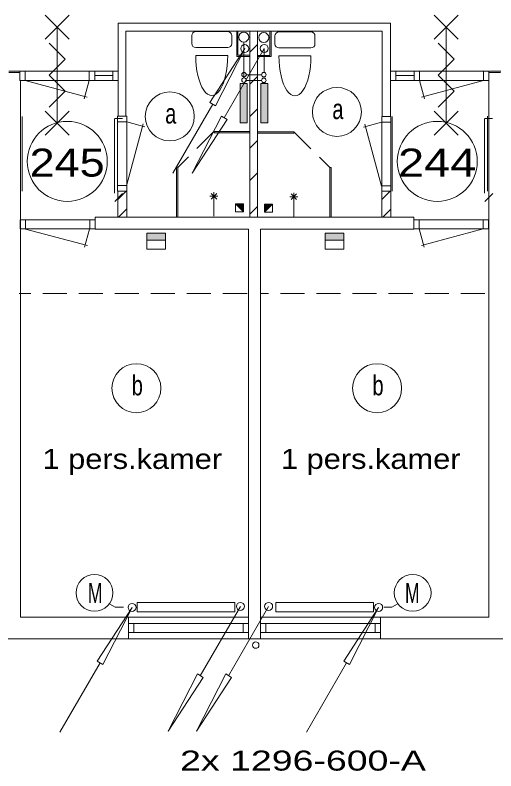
# Model space of a CAD drawing. Extents: x 295824 to 414724, y 24924 to 109024.
# Drawn here: x 314024 to 320029, y 85900 to 95351 of the extents above; entities that cross this region are included whole.
import ezdxf
from ezdxf.enums import TextEntityAlignment as Align

# ---------------------------------------------------------------- set-up
doc = ezdxf.new("R2010")
doc.units = 0
doc.header["$LTSCALE"] = 100
doc.linetypes.add('LONG_DASHED', pattern=[7.5, 6, -1.5])
doc.linetypes.add('MEDIUM_DASHED', pattern=[4.5, 3, -1.5])
doc.layers.add('16', color=7, linetype='Continuous', lineweight=13)
doc.layers.add('61', color=7, linetype='Continuous', lineweight=13)

msp = doc.modelspace()

# ---------------------------------------------------------------- hatches: boundary and pattern name
at = {"layer": '16'}
for points in [[(316835.4, 94004.5), (316920.8, 94004.5), (316920.8, 94496.7), (316835.4, 94496.7)], [(317094.6, 94004.5), (317180, 94004.5), (317180, 94496.7), (317094.6, 94496.7)], [(315902.2, 92624.5), (315670.7, 92624.5), (315670.7, 92538), (315902.2, 92538)], [(318129.9, 92624.5), (317898.4, 92624.5), (317898.4, 92538), (318129.9, 92538)]]:
    msp.add_hatch(color=256, dxfattribs=at).paths.add_polyline_path(points)
at = {"layer": '61'}
for points in [[(316775.3, 92991.3), (316875.3, 92891.3), (316875.3, 92991.3)], [(317237.7, 92985.9), (317137.7, 92885.9), (317137.7, 92985.9)]]:
    msp.add_hatch(color=256, dxfattribs=at).paths.add_polyline_path(points)

# ---------------------------------------------------------------- linework, layer by layer
at = {"layer": '16'}
for p, q in [((316882.7, 95010.5), (316882.7, 94570.9)), ((317136.2, 94934), (316636.2, 94068)), ((317103, 94535.5), (316911.2, 94535.5)), ((315992.3, 93373.3), (316492.3, 94239.3)), ((315670.7, 92538), (315670.7, 92424.1)), ((317898.4, 92538), (317898.4, 92424.1)), ((316837.4, 87956.8), (316337.4, 87090.8)), ((317190.8, 87956.8), (316690.8, 87090.8)), ((314584.5, 86385.7), (315084.5, 87251.7)), ((317664.9, 86385.7), (318164.9, 87251.7))]:
    msp.add_line(p, q, dxfattribs=at)
at = {"layer": '16', "linetype": 'LONG_DASHED'}
for p, q in [((317133.8, 94929.7), (317133.8, 94632)), ((316911.4, 94606.2), (317102.9, 94606.2))]:
    msp.add_line(p, q, dxfattribs=at)
at = {"layer": '16'}
for points in [[(316892.3, 94932.3), (316528.3, 94218.3), (316456.3, 94260.3)], [(316835.4, 94004.5), (316920.8, 94004.5), (316920.8, 94496.7), (316835.4, 94496.7)], [(317094.6, 94004.5), (317180, 94004.5), (317180, 94496.7), (317094.6, 94496.7)], [(316236.2, 93375), (316600.2, 94089), (316672.2, 94047)], [(315902.2, 92624.5), (315670.7, 92624.5), (315670.7, 92538), (315902.2, 92538)], [(318129.9, 92624.5), (317898.4, 92624.5), (317898.4, 92538), (318129.9, 92538)], [(315547.4, 88006.2), (316766.8, 88006.2), (316766.8, 87888.3), (315547.4, 87888.3)], [(317279.7, 88006.2), (318499, 88006.2), (318499, 87888.3), (317279.7, 87888.3)], [(315484.5, 87944.7), (315120.5, 87230.7), (315048.5, 87272.7)], [(318564.9, 87944.7), (318200.9, 87230.7), (318128.9, 87272.7)], [(315937.4, 86397.8), (316301.4, 87111.8), (316373.4, 87069.8)], [(316290.8, 86397.8), (316654.8, 87111.8), (316726.8, 87069.8)]]:
    msp.add_lwpolyline(points, close=True, dxfattribs=at)
for points in [[(315902.2, 92538), (315902.2, 92424.1), (315670.7, 92424.1)], [(318129.9, 92538), (318129.9, 92424.1), (317898.4, 92424.1)], [(315376.1, 87947.9), (315273.6, 87947.9), (315207.1, 87986.3)], [(318628.8, 87947.9), (318731.4, 87947.9), (318797.8, 87986.3)]]:
    msp.add_lwpolyline(points, dxfattribs=at)
for centre, radius in [((316892.3, 94932), 50), ((317136.2, 94934.3), 50), ((316883.5, 94606.2), 27.9), ((317130.9, 94606.2), 27.9), ((316883.5, 94538.4), 27.9), ((317130.9, 94535.5), 27.9), ((315015.6, 88125.9), 229.9), ((318989.4, 88125.9), 229.9), ((315484.5, 87944.4), 50), ((316837.4, 87957.1), 50), ((317190.8, 87957.1), 50), ((318564.9, 87944.4), 50)]:
    msp.add_circle(centre, radius, dxfattribs=at)
at = {"layer": '61'}
for p, q in [((314400.4, 95051.1), (314700.4, 95351.1)), ((314700.4, 95051.1), (314400.4, 95351.1)), ((319256.2, 95051.1), (319556.2, 95351.1)), ((319556.2, 95051.1), (319256.2, 95351.1)), ((314550.4, 95201.1), (314550.4, 94001.1)), ((319406.2, 95201.1), (319406.2, 94001.1)), ((315407, 94086.3), (315407, 95148.4)), ((316230.2, 94995.4), (316230.2, 95095.4)), ((316280.2, 95145.4), (316680.2, 95145.4)), ((316730.2, 95095.4), (316730.2, 94995.4)), ((316807, 94848.4), (316807, 95148.4)), ((316957, 92823.4), (316957, 95148.4)), ((317053.3, 92823.4), (317053.3, 95148.4)), ((317207.1, 95147.9), (317207.1, 94847.9)), ((317269.6, 94990.5), (317269.6, 95090.5)), ((317319.6, 95140.5), (317719.6, 95140.5)), ((317769.6, 95090.5), (317769.6, 94990.5)), ((317052.8, 94982.4), (316957, 94886.7)), ((316680.2, 94945.4), (316280.2, 94945.4)), ((317719.6, 94940.5), (317319.6, 94940.5)), ((316280.2, 94845.4), (316680.2, 94845.4)), ((316957, 94848.4), (316807, 94848.4)), ((317207.1, 94847.9), (317057.1, 94847.9)), ((317319.6, 94840.5), (317719.6, 94840.5)), ((313944.8, 94648.3), (314086, 94648.3)), ((313944.8, 94633.3), (314086, 94633.3)), ((314150.8, 94648.3), (314150.8, 94534.3)), ((314950.8, 94648.3), (314950.8, 94534.3)), ((315017.8, 94648.3), (315017.8, 94534.3)), ((315243.8, 94648.3), (315243.8, 94534.3)), ((318712.3, 94084.9), (318712.3, 94650.7)), ((318780.5, 94648.3), (318780.5, 94534.3)), ((319006.5, 94648.3), (319006.5, 94534.3)), ((319073.5, 94648.3), (319073.5, 94534.3)), ((319873.5, 94648.3), (319873.5, 94534.3)), ((319944.4, 94633.3), (320085.5, 94633.3)), ((319949.3, 94648.3), (320090.5, 94648.3)), ((314090.1, 94533.5), (314090.1, 87823.4)), ((314150.1, 94533.7), (314922.8, 94326.6)), ((314948.5, 94533.1), (314887.7, 94306.2)), ((315243.8, 94594.2), (315017.8, 94594.2)), ((315312.3, 94086.3), (315312.3, 94548.4)), ((317052.8, 94581.5), (316957, 94485.8)), ((318780.5, 94594.2), (319006.5, 94594.2)), ((319075.8, 94533.1), (319136.6, 94306.2)), ((319874.2, 94533.7), (319101.5, 94326.6)), ((319940.1, 94548.4), (319940.1, 87823.4)), ((314400.4, 93851.1), (314700.4, 94151.1)), ((314700.4, 93851.1), (314400.4, 94151.1)), ((317052.8, 94178.2), (316957, 94082.4)), ((319256.2, 93851.1), (319556.2, 94151.1)), ((319556.2, 93851.1), (319256.2, 94151.1)), ((314112.5, 93148.9), (314112.5, 94081.3)), ((315264.9, 93123.7), (315264.9, 94057.7)), ((315367.2, 94058.5), (315272.4, 94058.5)), ((315304.8, 93151.5), (315304.8, 94085.5)), ((315407, 94086.3), (315312.3, 94086.3)), ((318712.3, 94084.9), (318607, 94084.9)), ((318718.2, 93148.9), (318718.2, 94081.3)), ((318734.1, 93148.9), (318734.1, 94081.3)), ((319886.5, 93123.7), (319886.5, 94057.7)), ((319988.8, 94058.5), (319894, 94058.5)), ((319926.4, 93151.5), (319926.4, 94085.5)), ((315304.8, 94018.5), (315418.8, 94018.5)), ((315416.8, 93217.8), (315623.9, 93990.5)), ((315417.5, 94016.2), (315644.3, 93955.4)), ((318600.4, 94011.9), (318373.6, 93951.2)), ((318601.1, 93213.5), (318394, 93986.3)), ((318718.2, 94014.3), (318604.2, 94014.3)), ((316958.2, 93897), (316508.7, 93897)), ((316508.7, 93897), (316508.7, 93879)), ((316957.8, 93879), (316508.7, 93879)), ((317054.8, 93891.6), (317504.3, 93891.6)), ((317055.2, 93873.6), (317504.3, 93873.6)), ((317504.3, 93891.6), (317504.3, 93873.6)), ((317052.8, 93782.2), (316957, 93686.4)), ((316057.8, 92829), (316057.8, 93449.5)), ((317052.8, 93377.6), (316957, 93281.8)), ((317955.2, 92823.6), (317955.2, 93444.1)), ((315304.8, 93218.5), (315418.8, 93218.5)), ((318718.2, 93214.3), (318604.2, 93214.3)), ((315367.3, 93118.9), (315267.6, 93019.2)), ((315418.2, 93151.5), (315304.2, 93151.5)), ((315417.5, 93148), (315307.5, 93148)), ((315307.5, 93148), (315307.5, 92823.9)), ((315407.2, 93146.8), (315307.5, 93047.1)), ((315417.5, 93148), (315417.5, 92823.9)), ((316543, 93050.1), (316472.3, 93120.8)), ((316543, 93120.8), (316472.3, 93050.1)), ((316507.6, 93035.5), (316507.6, 93135.5)), ((317470, 93044.8), (317540.7, 93115.5)), ((317470, 93115.5), (317540.7, 93044.8)), ((317505.4, 93030.1), (317505.4, 93130.1)), ((318705.6, 93146.8), (318605.9, 93047.1)), ((318716.4, 93148), (318606.5, 93148)), ((318606.5, 93148), (318606.5, 92823.9)), ((318716.4, 93148), (318716.4, 92823.9)), ((319988.9, 93118.9), (319889.2, 93019.2)), ((316557.6, 93085.5), (316457.6, 93085.5)), ((316507.6, 93035.5), (316507.6, 92835.5)), ((317455.4, 93080.1), (317555.4, 93080.1)), ((317505.4, 93030.1), (317505.4, 92830.1)), ((315415.8, 92924.2), (315316.1, 92824.5)), ((317052.8, 92959.5), (316957, 92863.7)), ((318717.9, 92924.2), (318618.2, 92824.5)), ((315417.5, 92823.9), (315307.5, 92823.9)), ((318716.4, 92823.9), (318606.5, 92823.9)), ((314155.4, 92790.9), (314155.4, 92676.9)), ((314955.4, 92790.9), (314955.4, 92676.9)), ((315022.4, 92790.9), (315022.4, 92676.9)), ((319003.1, 92791.9), (319003.1, 92677.9)), ((319070.1, 92791.9), (319070.1, 92677.9)), ((319870.1, 92791.9), (319870.1, 92677.9)), ((314154.7, 92676.2), (314927.4, 92469.2)), ((314953.1, 92675.6), (314892.3, 92448.8)), ((316940.1, 87553.4), (316940.1, 92673.4)), ((317090.1, 87553.4), (317090.1, 92673.4)), ((319072.4, 92676.7), (319133.2, 92449.8)), ((319870.9, 92677.3), (319098.1, 92470.3)), ((314090.1, 87823.4), (316940.1, 87823.4)), ((315441, 87552.1), (315441, 87822.1)), ((319940.1, 87823.4), (317090.1, 87823.4)), ((318589.5, 87552.2), (318589.5, 87822.2)), ((315508.1, 87630.5), (315508.1, 87744.3)), ((316873.1, 87629.9), (316873.1, 87743.9)), ((317156.6, 87630.8), (317156.6, 87744.8)), ((318520.9, 87630.5), (318520.9, 87744.2)), ((326233, 87553.4), (307806, 87553.4))]:
    msp.add_line(p, q, dxfattribs=at)
at = {"layer": '61', "linetype": 'MEDIUM_DASHED'}
for p, q in [((316506.6, 93896.5), (316059.7, 93449.6)), ((317506.4, 93891.2), (317953.3, 93444.3)), ((316920.4, 91870), (314073.3, 91870)), ((319889.8, 91870), (317090.1, 91870))]:
    msp.add_line(p, q, dxfattribs=at)
at = {"layer": '61'}
for points in [[(318712.3, 94648.4), (318712.3, 95248.4), (315312.3, 95248.4), (315312.3, 94648.4)], [(318607, 94084.9), (318607, 95148.4), (315407, 95148.4)], [(316957, 94833.4), (316792, 94833.4), (316792, 95148.4)], [(317222.1, 95147.9), (317222.1, 94832.9), (317057.1, 94832.9)], [(314450.4, 95001.1), (314650.4, 94801.1), (314450.4, 94601.1), (314650.4, 94401.1), (314450.4, 94201.1)], [(319306.2, 95001.1), (319506.2, 94801.1), (319306.2, 94601.1), (319506.2, 94401.1), (319306.2, 94201.1)], [(316039.8, 92829), (316039.8, 93449.5), (316057.8, 93449.5)], [(317973.2, 92823.6), (317973.2, 93444.1), (317955.2, 93444.1)], [(316875.3, 92891.3), (316875.3, 92991.3), (316775.3, 92991.3)], [(317137.7, 92885.9), (317137.7, 92985.9), (317237.7, 92985.9)], [(317087.3, 92673.4), (319002.3, 92673.4), (319002.3, 92823.4), (315022.9, 92823.4)], [(316937.3, 92673.4), (315022.9, 92673.4), (315022.9, 92823.4)], [(314088.4, 92790.9), (314088.4, 92676.9), (315022.4, 92676.9)], [(315022.4, 92790.9), (314088.4, 92790.9), (314088.4, 92676.9)], [(319937.1, 92791.9), (319937.1, 92677.9), (319003.1, 92677.9)], [(319003.1, 92791.9), (319937.1, 92791.9), (319937.1, 92677.9)]]:
    msp.add_lwpolyline(points, dxfattribs=at)
for points in [[(315310.8, 94648.3), (315310.8, 94534.3), (314083.8, 94534.3), (314083.8, 94648.3)], [(315310.9, 94648.3), (315310.9, 94534.3), (314083.9, 94534.3), (314083.9, 94648.3)], [(319940.5, 94648.3), (319940.5, 94534.3), (318714.1, 94534.3), (318714.1, 94648.3)], [(319940.5, 94648.3), (319940.5, 94534.3), (318714.1, 94534.3), (318714.1, 94648.3)], [(315304.8, 93151.5), (315304.8, 94085.5), (315418.8, 94085.5), (315418.8, 93151.5)], [(318718.2, 94082.2), (318604.2, 94082.2), (318604.2, 93148.2), (318718.2, 93148.2)], [(316875.3, 92891.3), (316775.3, 92891.3), (316775.3, 92991.3)], [(316775.3, 92991.3), (316875.3, 92891.3), (316875.3, 92991.3)], [(317137.7, 92885.9), (317237.7, 92885.9), (317237.7, 92985.9)], [(317237.7, 92985.9), (317137.7, 92885.9), (317137.7, 92985.9)], [(315441.2, 87630.3), (315441.2, 87744.3), (316939.9, 87744.3), (316939.9, 87630.3)], [(317090.2, 87630.5), (317090.2, 87744.5), (318589.6, 87744.5), (318589.6, 87630.5)]]:
    msp.add_lwpolyline(points, close=True, dxfattribs=at)
for centre, radius in [((316879.5, 95075.9), 62.5), ((317129.5, 95070.4), 62.5), ((318044.2, 94140.2), 306.3), ((315956.1, 94084.5), 306.3), ((314675.2, 93521.8), 500), ((319296.8, 93521.8), 500), ((315538.5, 90685.4), 306.3), ((318545.3, 90685.4), 306.3), ((317029.6, 87473.2), 40)]:
    msp.add_circle(centre, radius, dxfattribs=at)
for centre, start, end in [((316280.2, 95095.4), 90, 180), ((316680.2, 95095.4), 0, 90), ((317319.6, 95090.5), 90, 180), ((317719.6, 95090.5), 0, 90), ((316280.2, 94995.4), 180, 270), ((316680.2, 94995.4), 270, 0), ((317319.6, 94990.5), 180, 270), ((317719.6, 94990.5), 270, 0)]:
    msp.add_arc(centre, 50, start, end, dxfattribs=at)
for centre in [(316480.2, 94845.4), (317519.6, 94840.5)]:
    msp.add_ellipse(centre, major_axis=(0, -500), ratio=0.4, start_param=4.712389, end_param=7.853982, dxfattribs=at)

# ---------------------------------------------------------------- texts
at = {"layer": '16'}
for s, width, p in [('M', 0.65, (314933.3, 87999.3)), ('M', 0.65, (318894.5, 87999.3)), ('2x 1296-600-A', 1.4, (316084.4, 85903.8))]:
    msp.add_text(s, height=250, dxfattribs=dict(at, width=width)).set_placement(p)
at = {"layer": '61'}
for s, width, p in [('a', 0.75, (317986.2, 94051)), ('a', 0.75, (315898.1, 93995.3)), ('b', 0.75, (315480.5, 90596.2)), ('b', 0.75, (318487.3, 90596.2)), ('1 pers.kamer', 1.15, (314366.1, 89676.2)), ('1 pers.kamer', 1.15, (317344.1, 89676.2))]:
    msp.add_text(s, height=250, dxfattribs=dict(at, width=width)).set_placement(p)
for s, width, p in [('245', 1.2, (314673.7, 93331.9)), ('244', 1.25, (319295.3, 93331.9))]:
    msp.add_text(s, height=350, dxfattribs=dict(at, width=width)).set_placement(p, align=Align.CENTER)

doc.saveas('drawing.dxf')
